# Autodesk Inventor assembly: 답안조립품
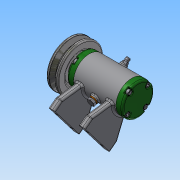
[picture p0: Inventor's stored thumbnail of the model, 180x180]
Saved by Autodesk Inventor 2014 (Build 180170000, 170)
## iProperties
Created: 2018-05
Part Number: 답안조립품
Document SubType Name: Assembly
Designer: NET
Author: NET
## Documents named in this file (16)
- C:\Users\NET\Desktop\답안조립품.iam
- C:\Users\NET\Desktop\본체.ipt
- C:\Users\NET\Desktop\480507V1030\베어링 6002.ipt
- C:\Users\NET\Desktop\480507V1030\뒤커버.ipt
- C:\Users\NET\Desktop\480507V1030\앞커버.ipt
- C:\Users\NET\Desktop\480507V1030\축.ipt
- C:\Users\NET\Desktop\480507V1030\오일 실 15 25 7.ipt
- C:\Users\NET\Desktop\480507V1030\키 3x3x12.ipt
- C:\Users\NET\Desktop\480507V1030\V벨트풀리.ipt
- C:\Users\NET\Desktop\480507V1030\와셔 8x17.ipt
- C:\Users\NET\Desktop\480507V1030\스프링와셔 8.ipt
- C:\Users\NET\Desktop\480507V1030\너트 M8.ipt
- C:\Users\NET\Desktop\480507V1030\와셔 6x11.5.ipt
- C:\Users\NET\Desktop\480507V1030\볼트 M6x8.ipt
- C:\Users\NET\Desktop\480507V1030\니플 M6x0.75.ipt
- C:\Users\NET\Desktop\480507V1030\볼트 M4x12.ipt
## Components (1 placed, 1 different names)
1. V벨트풀리:1
